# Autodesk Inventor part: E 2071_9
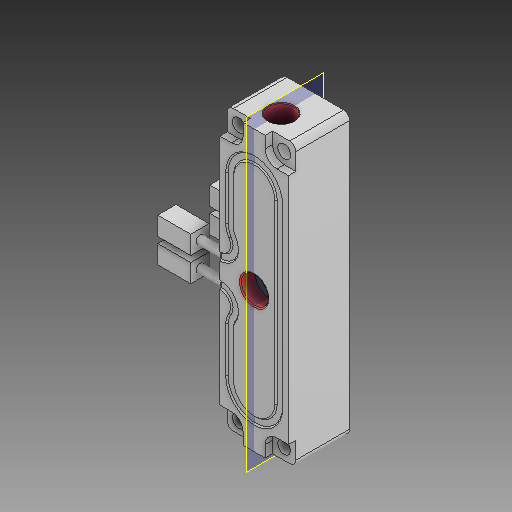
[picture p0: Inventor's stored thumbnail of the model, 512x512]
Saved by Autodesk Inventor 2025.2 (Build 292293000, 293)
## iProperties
Created: 2025-04
Part Number: E 2071_9
Material: Všeobecné
Document SubType Name: Modeling
Designer: Patrik
Density: 1 g/cm^3
Appearance: Výchozí
Mass: 556.036 g
Surface Area: 844.733 cm^2
Volume: 556.036 cm^3
Author: Patrik
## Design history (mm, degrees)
feature "Base1"
node "Pracovní rovina1"
node "Těleso1"
